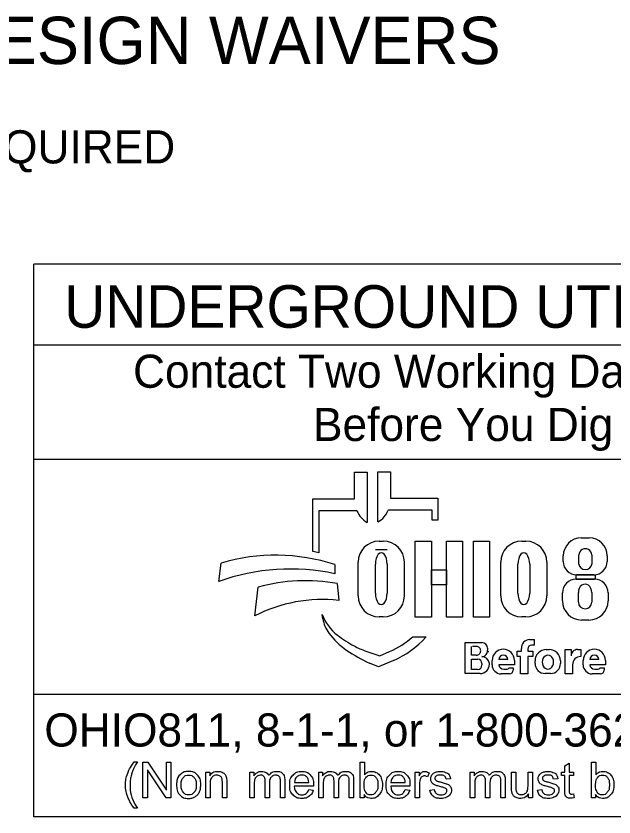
# Model space of a CAD drawing. Extents: x 43.1 to 77.1, y 2.7 to 24.7.
# Drawn here: x 46.033 to 48.562, y 4.801 to 8.187 of the extents above; entities that cross this region are included whole.
import ezdxf

# ---------------------------------------------------------------- set-up
doc = ezdxf.new("R2010")
doc.units = 0
doc.layers.add('SH_Data', color=7, linetype='Continuous')
doc.layers.add('SH_Text', color=7, linetype='Continuous')

msp = doc.modelspace()

# ---------------------------------------------------------------- linework, layer by layer
at = {"layer": 'SH_Data'}
for p, q in [((46.1084, 4.8008), (46.1084, 7.1383)), ((50.3584, 7.1383), (46.1084, 7.1383)), ((46.1084, 6.7967), (50.3584, 6.7967)), ((46.1084, 6.3134), (50.3584, 6.3134)), ((50.3584, 5.3187), (46.1084, 5.3187)), ((50.3584, 4.8008), (46.1084, 4.8008))]:
    msp.add_line(p, q, dxfattribs=at)
at = {"layer": 'SH_Text'}
for p, q in [((47.4645, 6.1463), (47.4645, 6.2578)), ((47.4645, 6.2578), (47.5181, 6.2578)), ((47.5181, 6.2578), (47.5181, 6.0457)), ((47.5638, 6.0481), (47.5638, 6.2601)), ((47.5638, 6.2601), (47.6174, 6.2601)), ((47.6174, 6.2601), (47.6174, 6.1487)), ((47.2885, 5.9224), (47.2885, 6.1463)), ((47.2885, 6.1463), (47.4645, 6.1463)), ((47.6174, 6.1487), (47.8167, 6.1487)), ((47.8167, 6.1487), (47.8167, 6.0548)), ((47.3137, 6.0949), (47.3137, 5.918)), ((47.4749, 6.0949), (47.3137, 6.0949)), ((47.7934, 6.0972), (47.607, 6.0972)), ((47.7934, 6.0548), (47.7934, 6.0972)), ((47.8167, 6.0548), (47.7934, 6.0548)), ((47.5694, 5.9671), (47.586, 5.9671)), ((48.1725, 5.9671), (48.189, 5.9671)), ((48.424, 5.9811), (48.4568, 5.9811)), ((47.6027, 5.9301), (47.5529, 5.9301)), ((48.3477, 5.8805), (48.3477, 5.9048)), ((48.4139, 5.8691), (48.4139, 5.9084)), ((48.468, 5.9084), (48.468, 5.8691)), ((48.5331, 5.9048), (48.5331, 5.8805)), ((46.8911, 5.7961), (46.9005, 5.8743)), ((47.3818, 5.8678), (47.3818, 5.8289)), ((47.48, 5.7357), (47.48, 5.8777)), ((47.5529, 5.7471), (47.5529, 5.8694)), ((47.6027, 5.8694), (47.6027, 5.7471)), ((47.6754, 5.8777), (47.6754, 5.7357)), ((48.083, 5.7357), (48.083, 5.8777)), ((48.1559, 5.7471), (48.1559, 5.8694)), ((48.2057, 5.8694), (48.2057, 5.7471)), ((48.2785, 5.8777), (48.2785, 5.7357)), ((48.4771, 5.8245), (48.4037, 5.8245)), ((48.4019, 5.8062), (48.4792, 5.8062)), ((47.043, 5.6516), (47.0576, 5.7717)), ((47.3918, 5.7872), (47.398, 5.7162)), ((48.344, 5.7143), (48.344, 5.7483)), ((48.4115, 5.7083), (48.4115, 5.7493)), ((48.4684, 5.7493), (48.4684, 5.7083)), ((48.5371, 5.7483), (48.5371, 5.7143)), ((47.3306, 5.6387), (47.3276, 5.6566)), ((47.586, 5.6462), (47.5694, 5.6462)), ((48.189, 5.6462), (48.1725, 5.6462)), ((48.4562, 5.6334), (48.425, 5.6334)), ((47.7109, 5.5628), (47.7684, 5.5628)), ((47.9322, 5.4071), (47.9322, 5.5378)), ((47.9322, 5.5378), (48.0034, 5.5378)), ((47.9602, 5.4843), (47.9602, 5.5212)), ((47.9854, 5.5212), (47.9641, 5.5212)), ((48.2048, 5.5506), (48.2243, 5.5506)), ((48.2243, 5.5271), (48.2141, 5.5271)), ((48.2243, 5.5506), (48.2243, 5.5276)), ((47.5125, 5.5024), (47.5719, 5.482)), ((47.5719, 5.482), (47.613, 5.4998)), ((48.0272, 5.514), (48.0272, 5.5061)), ((48.1522, 5.4792), (48.1522, 5.5022)), ((48.1522, 5.5022), (48.1715, 5.5022)), ((48.1715, 5.5022), (48.1715, 5.5127)), ((48.1976, 5.5106), (48.1976, 5.5022)), ((48.1976, 5.5022), (48.2192, 5.5022)), ((48.2192, 5.5022), (48.2192, 5.4792)), ((48.276, 5.5088), (48.2882, 5.5088)), ((48.3563, 5.4059), (48.3563, 5.5086)), ((48.3563, 5.5086), (48.3808, 5.5086)), ((48.3808, 5.5086), (48.3808, 5.4817)), ((48.4081, 5.5086), (48.422, 5.5086)), ((48.422, 5.5086), (48.422, 5.4789)), ((47.5659, 5.4349), (47.5286, 5.4514)), ((47.6292, 5.4624), (47.5659, 5.4349)), ((47.9796, 5.4843), (47.9602, 5.4843)), ((47.9602, 5.4249), (47.9602, 5.4678)), ((47.9602, 5.4678), (47.9857, 5.4678)), ((48.0468, 5.4438), (48.0468, 5.4623)), ((48.1134, 5.4662), (48.0748, 5.4662)), ((48.1413, 5.4623), (48.1413, 5.4446)), ((48.1671, 5.4792), (48.1522, 5.4792)), ((48.1671, 5.4059), (48.1671, 5.4792)), ((48.2192, 5.4792), (48.1976, 5.4792)), ((48.1976, 5.4792), (48.1976, 5.4059)), ((48.2282, 5.4502), (48.2282, 5.461)), ((48.336, 5.461), (48.336, 5.4502)), ((48.4317, 5.4438), (48.4317, 5.4623)), ((48.4983, 5.4662), (48.4598, 5.4662)), ((48.5262, 5.4623), (48.5262, 5.4446)), ((47.9855, 5.4249), (47.9602, 5.4249)), ((48.0039, 5.4496), (48.0039, 5.4433)), ((48.0352, 5.4467), (48.0352, 5.4464)), ((48.1413, 5.4446), (48.0749, 5.4446)), ((48.0958, 5.4254), (48.1099, 5.4254)), ((48.1185, 5.4309), (48.1354, 5.4309)), ((48.1354, 5.4309), (48.1354, 5.4211)), ((48.3868, 5.444), (48.3868, 5.4059)), ((48.5262, 5.4446), (48.4598, 5.4446)), ((48.4807, 5.4254), (48.4949, 5.4254)), ((48.5034, 5.4309), (48.5203, 5.4309)), ((48.5203, 5.4309), (48.5203, 5.4211)), ((47.9959, 5.4071), (47.9322, 5.4071)), ((48.1201, 5.4059), (48.0847, 5.4059)), ((48.1976, 5.4059), (48.1671, 5.4059)), ((48.2932, 5.4074), (48.271, 5.4074)), ((48.3868, 5.4059), (48.3563, 5.4059)), ((48.5051, 5.4059), (48.4697, 5.4059))]:
    msp.add_line(p, q, dxfattribs=at)
for points in [[(47.7219, 5.9661), (47.7898, 5.9661), (47.7898, 5.6461), (47.7219, 5.6461)], [(47.854, 5.9661), (47.922, 5.9661), (47.922, 5.6461), (47.854, 5.6461)], [(47.9673, 5.9661), (48.0361, 5.9661), (48.0361, 5.6461), (47.9673, 5.6461)], [(47.7898, 5.8462), (47.854, 5.8462), (47.854, 5.7822), (47.7898, 5.7822)], [(48.4016, 5.8246), (48.4832, 5.8246), (48.4832, 5.8061), (48.4016, 5.8061)]]:
    msp.add_lwpolyline(points, close=True, dxfattribs=at)
for points in [[(46.533, 5.0346), (46.5462, 5.0346)], [(46.5698, 4.8819), (46.5698, 5.0321), (46.5901, 5.0321), (46.6691, 4.9142), (46.6691, 5.0321), (46.6881, 5.0321), (46.6881, 4.8819), (46.6678, 4.8819), (46.5888, 4.9999), (46.5888, 4.8819), (46.5698, 4.8819)], [(47.5052, 4.8819), (47.4882, 4.8819), (47.4882, 5.0321), (47.5066, 5.0321), (47.5066, 4.9786)], [(48.3542, 4.9138), (48.3542, 4.9765), (48.3406, 4.9765), (48.3406, 4.9908), (48.3542, 4.9908), (48.3542, 5.0177), (48.3726, 5.0288), (48.3726, 4.9908), (48.391, 4.9908), (48.391, 4.9765), (48.3726, 4.9765), (48.3726, 4.9127)], [(48.4843, 4.8819), (48.4673, 4.8819), (48.4673, 5.0321), (48.4857, 5.0321), (48.4857, 4.9786)], [(46.8357, 4.8819), (46.8357, 4.9908), (46.8523, 4.9908), (46.8523, 4.9753)], [(47.0222, 4.8819), (47.0222, 4.9908), (47.0386, 4.9908), (47.0386, 4.9754)], [(47.3135, 4.8819), (47.3135, 4.9908), (47.33, 4.9908), (47.33, 4.9754)], [(47.7213, 4.8819), (47.7213, 4.9908), (47.7379, 4.9908), (47.7379, 4.9743)], [(47.7804, 4.9873), (47.7739, 4.9702)], [(47.9545, 4.8819), (47.9545, 4.9908), (47.971, 4.9908), (47.971, 4.9754)], [(48.1288, 4.9234), (48.1288, 4.9908), (48.1473, 4.9908), (48.1473, 4.9305)], [(48.1985, 4.9325), (48.1985, 4.9908), (48.217, 4.9908), (48.217, 4.8819), (48.2005, 4.8819)], [(46.9241, 4.9488), (46.9241, 4.8819), (46.9057, 4.8819), (46.9057, 4.9481)], [(47.1052, 4.9451), (47.1052, 4.8819), (47.0868, 4.8819), (47.0868, 4.9526)], [(47.1697, 4.9566), (47.1697, 4.8819), (47.1512, 4.8819), (47.1512, 4.9504)], [(47.2108, 4.9467), (47.2715, 4.9467)], [(47.3966, 4.9451), (47.3966, 4.8819), (47.3782, 4.8819), (47.3782, 4.9526)], [(47.461, 4.9566), (47.461, 4.8819), (47.4426, 4.8819), (47.4426, 4.9504)], [(47.6188, 4.9467), (47.6795, 4.9467)], [(47.8703, 4.9626), (47.8522, 4.9602)], [(48.0376, 4.9451), (48.0376, 4.8819), (48.0192, 4.8819), (48.0192, 4.9526)], [(48.102, 4.9566), (48.102, 4.8819), (48.0836, 4.8819), (48.0836, 4.9504)], [(48.3249, 4.9626), (48.3068, 4.9602)], [(46.8542, 4.9413), (46.8542, 4.8819), (46.8357, 4.8819)], [(47.0406, 4.9384), (47.0406, 4.8819), (47.0222, 4.8819)], [(47.2909, 4.9316), (47.2097, 4.9316)], [(47.2713, 4.9171), (47.2904, 4.9147)], [(47.332, 4.9384), (47.332, 4.8819), (47.3135, 4.8819)], [(47.6989, 4.9316), (47.6177, 4.9316)], [(47.6793, 4.9171), (47.6984, 4.9147)], [(47.7397, 4.9389), (47.7397, 4.8819), (47.7213, 4.8819)], [(47.7839, 4.9145), (47.8021, 4.9173)], [(47.973, 4.9384), (47.973, 4.8819), (47.9545, 4.8819)], [(48.2385, 4.9145), (48.2567, 4.9173)], [(47.5052, 4.8956), (47.5052, 4.8819)], [(48.2005, 4.8819), (48.2005, 4.898)], [(48.391, 4.8984), (48.3937, 4.8821)], [(48.4843, 4.8956), (48.4843, 4.8819)], [(46.5462, 4.8378), (46.533, 4.8378)]]:
    msp.add_lwpolyline(points, dxfattribs=at)
for centre, radius, start, end in [((47.5662, 6.1317), 0.0985, 201.9296, 240.7469), ((47.5156, 6.134), 0.0985, 299.2531, 338.0704), ((47.5694, 5.8777), 0.0895, 90, 180), ((47.586, 5.8777), 0.0895, 0, 90), ((48.1725, 5.8777), 0.0895, 90, 180), ((48.189, 5.8777), 0.0895, 0, 90), ((48.424, 5.9048), 0.0763, 90, 180), ((48.4568, 5.9048), 0.0763, 0, 90), ((47.1306, 5.0882), 0.8191, 72.1402, 106.3144), ((47.1604, 5.1135), 0.8191, 79.2074, 81.0007), ((48.4037, 5.8805), 0.056, 180, 270), ((48.4771, 5.8805), 0.056, 270, 0), ((47.1937, 4.9571), 0.8919, 77.8238, 109.8274), ((47.2576, 5.0674), 0.7322, 79.44, 105.8467), ((48.4019, 5.7483), 0.0579, 90, 180), ((48.4792, 5.7483), 0.0579, 0, 90), ((47.5694, 5.7357), 0.0895, 180, 270), ((47.586, 5.7357), 0.0895, 270, 0), ((48.1725, 5.7357), 0.0895, 180, 270), ((48.189, 5.7357), 0.0895, 270, 0), ((47.3296, 5.0842), 0.6357, 83.8248, 116.8021), ((48.425, 5.7143), 0.081, 180, 270), ((48.4562, 5.7143), 0.081, 270, 0), ((47.515, 5.7287), 0.2008, 201.0457, 232.5314), ((47.4719, 5.6628), 0.1433, 189.6817, 216.0884), ((47.6056, 5.7602), 0.3088, 216.0884, 235.7167), ((47.7075, 5.9799), 0.5173, 232.5314, 241.794), ((47.4696, 5.8302), 0.3602, 293.4582, 312.0712), ((47.4696, 5.8302), 0.401, 293.4582, 317.8286), ((47.6223, 5.8211), 0.3371, 241.794, 250.9821), ((47.9815, 5.5044), 0.0169, 357.8325, 90), ((48.0034, 5.514), 0.0238, 0, 90), ((48.2048, 5.517), 0.0335, 90, 187.5187), ((48.2141, 5.5106), 0.0165, 90, 180), ((47.7721, 6.0045), 0.6044, 235.7167, 246.2325), ((47.9796, 5.503), 0.0187, 270, 2.0582), ((48.003, 5.5033), 0.0243, 270, 6.6529), ((48.0136, 5.5018), 0.0175, 347.4023, 0), ((48.094, 5.4623), 0.0473, 0, 180), ((48.276, 5.461), 0.0478, 90, 180), ((48.2882, 5.461), 0.0478, 0, 90), ((48.4077, 5.4817), 0.0269, 89.2449, 180), ((48.479, 5.4623), 0.0473, 0, 180), ((47.9857, 5.4496), 0.0181, 0, 90), ((48.0031, 5.4469), 0.0321, 4.0748, 90), ((48.0023, 5.4467), 0.033, 0, 11.7502), ((48.0941, 5.4652), 0.0193, 2.9632, 177.0368), ((48.4217, 5.444), 0.0349, 89.6033, 180), ((48.479, 5.4652), 0.0193, 2.9632, 177.0368), ((47.9855, 5.4433), 0.0184, 270, 0), ((47.9959, 5.4464), 0.0393, 270, 0), ((48.0847, 5.4438), 0.038, 180, 270), ((48.0958, 5.4464), 0.021, 184.827, 270), ((48.1099, 5.4347), 0.00938, 270, 335.9979), ((48.1201, 5.4211), 0.0152, 270, 0), ((48.271, 5.4502), 0.0428, 180, 270), ((48.2932, 5.4502), 0.0428, 270, 0), ((48.4697, 5.4438), 0.038, 180, 270), ((48.4807, 5.4464), 0.021, 184.827, 270), ((48.4949, 5.4347), 0.00938, 270, 335.9979), ((48.5051, 5.4211), 0.0152, 270, 0)]:
    msp.add_arc(centre, radius, start, end, dxfattribs=at)
for centre, major_axis, ratio, start_param, end_param in [((48.4409, 5.9084), (0.0271, 0), 0.969373, 0, 3.141593), ((47.5778, 5.8694), (0, 0.0484), 0.514403, 4.712389, 7.853982), ((48.1808, 5.8694), (0, 0.0484), 0.514403, 4.712389, 7.853982), ((48.4409, 5.8691), (0.0271, 0), 0.818453, 3.141593, 6.283185), ((48.4399, 5.7493), (0, 0.0358), 0.794529, 4.712389, 7.853982), ((47.5778, 5.7471), (0, 0.0484), 0.514403, 1.570796, 4.712389), ((48.1808, 5.7471), (0, 0.0484), 0.514403, 1.570796, 4.712389), ((48.4399, 5.7083), (0.0284, 0), 0.959837, 3.141593, 6.283185), ((48.2826, 5.4556), (0, 0.029), 0.832186, 4.712389, 7.853982), ((48.2826, 5.4556), (0, 0.0302), 0.797287, 1.570796, 4.712389)]:
    msp.add_ellipse(centre, major_axis=major_axis, ratio=ratio, start_param=start_param, end_param=end_param, dxfattribs=at)
for points in [[(46.533, 4.8378), (46.5178, 4.857), (46.5072, 4.8828), (46.4966, 4.9086), (46.4966, 4.9363), (46.4966, 4.9607), (46.5045, 4.983), (46.5138, 5.0089), (46.533, 5.0346)], [(46.5462, 5.0346), (46.5338, 5.0133), (46.5299, 5.0042), (46.5236, 4.9901), (46.52, 4.9747), (46.5156, 4.9556), (46.5156, 4.9362), (46.5156, 4.8869), (46.5462, 4.8378)], [(46.7123, 4.9364), (46.7123, 4.9666), (46.729, 4.9811), (46.7431, 4.9932), (46.7632, 4.9932), (46.7857, 4.9932), (46.7999, 4.9785), (46.8141, 4.9638), (46.8141, 4.9379), (46.8141, 4.9169), (46.8078, 4.9049), (46.8015, 4.8929), (46.7895, 4.8862), (46.7775, 4.8795), (46.7632, 4.8795), (46.7404, 4.8795), (46.7263, 4.8942), (46.7123, 4.9088), (46.7123, 4.9364)], [(46.7313, 4.9364), (46.7313, 4.9155), (46.7404, 4.9051), (46.7494, 4.8947), (46.7632, 4.8947), (46.7769, 4.8947), (46.786, 4.9051), (46.7951, 4.9156), (46.7951, 4.937), (46.7951, 4.9572), (46.786, 4.9676), (46.7768, 4.978), (46.7632, 4.978), (46.7494, 4.978), (46.7404, 4.9676), (46.7313, 4.9573), (46.7313, 4.9364)], [(46.8523, 4.9753), (46.8643, 4.9932), (46.8869, 4.9932), (46.8968, 4.9932), (46.905, 4.9897), (46.9132, 4.9861), (46.9173, 4.9804), (46.9214, 4.9746), (46.9231, 4.9668), (46.9241, 4.9616), (46.9241, 4.9488)], [(46.9057, 4.9481), (46.9057, 4.9594), (46.9035, 4.9649), (46.9014, 4.9705), (46.8959, 4.9738), (46.8904, 4.9772), (46.883, 4.9772), (46.8713, 4.9772), (46.8627, 4.9697), (46.8542, 4.9622), (46.8542, 4.9413)], [(47.0386, 4.9754), (47.0438, 4.9834), (47.0523, 4.9883), (47.0608, 4.9932), (47.0716, 4.9932), (47.0837, 4.9932), (47.0915, 4.9882), (47.0992, 4.9831), (47.1024, 4.9741), (47.1153, 4.9932), (47.136, 4.9932), (47.1522, 4.9932), (47.161, 4.9842), (47.1697, 4.9753), (47.1697, 4.9566)], [(47.0868, 4.9526), (47.0868, 4.9649), (47.0823, 4.971), (47.0778, 4.9772), (47.0675, 4.9772), (47.0598, 4.9772), (47.0531, 4.9731), (47.0465, 4.969), (47.0436, 4.9611), (47.0406, 4.9532), (47.0406, 4.9384)], [(47.1512, 4.9504), (47.1512, 4.9615), (47.1495, 4.9664), (47.1477, 4.9712), (47.1429, 4.9742), (47.1382, 4.9772), (47.1319, 4.9772), (47.1204, 4.9772), (47.1128, 4.9695), (47.1052, 4.9619), (47.1052, 4.9451)], [(47.2904, 4.9147), (47.2859, 4.898), (47.2737, 4.8888), (47.2615, 4.8795), (47.2426, 4.8795), (47.2187, 4.8795), (47.2047, 4.8942), (47.1907, 4.9089), (47.1907, 4.9354), (47.1907, 4.9629), (47.2049, 4.978), (47.219, 4.9932), (47.2415, 4.9932), (47.2634, 4.9932), (47.2772, 4.9783), (47.291, 4.9635), (47.291, 4.9365), (47.291, 4.9349), (47.2909, 4.9316)], [(47.2715, 4.9467), (47.2703, 4.9605), (47.2646, 4.9674), (47.2558, 4.9781), (47.2417, 4.9781), (47.229, 4.9781), (47.2204, 4.9695), (47.2117, 4.961), (47.2108, 4.9467)], [(47.33, 4.9754), (47.3351, 4.9834), (47.3436, 4.9883), (47.3521, 4.9932), (47.363, 4.9932), (47.3751, 4.9932), (47.3828, 4.9882), (47.3906, 4.9831), (47.3937, 4.9741), (47.4067, 4.9932), (47.4274, 4.9932), (47.4436, 4.9932), (47.4523, 4.9842), (47.461, 4.9753), (47.461, 4.9566)], [(47.3782, 4.9526), (47.3782, 4.9649), (47.3737, 4.971), (47.3692, 4.9772), (47.3589, 4.9772), (47.3511, 4.9772), (47.3445, 4.9731), (47.3379, 4.969), (47.3349, 4.9611), (47.332, 4.9532), (47.332, 4.9384)], [(47.4426, 4.9504), (47.4426, 4.9615), (47.4408, 4.9664), (47.439, 4.9712), (47.4343, 4.9742), (47.4296, 4.9772), (47.4233, 4.9772), (47.4118, 4.9772), (47.4042, 4.9695), (47.3966, 4.9619), (47.3966, 4.9451)], [(47.505, 4.9372), (47.505, 4.9176), (47.5103, 4.9089), (47.519, 4.8947), (47.5338, 4.8947), (47.5459, 4.8947), (47.5547, 4.9052), (47.5635, 4.9157), (47.5635, 4.9365), (47.5635, 4.9578), (47.5551, 4.9679), (47.5466, 4.9781), (47.5347, 4.9781), (47.5226, 4.9781), (47.5138, 4.9676), (47.505, 4.9571), (47.505, 4.9372)], [(47.5066, 4.9786), (47.5183, 4.9932), (47.5364, 4.9932), (47.5464, 4.9932), (47.5554, 4.9891), (47.5644, 4.9851), (47.5702, 4.9778), (47.5759, 4.9705), (47.5792, 4.9601), (47.5825, 4.9498), (47.5825, 4.938), (47.5825, 4.9101), (47.5687, 4.8948), (47.5548, 4.8795), (47.5355, 4.8795), (47.5162, 4.8795), (47.5052, 4.8956)], [(47.6984, 4.9147), (47.6939, 4.898), (47.6817, 4.8888), (47.6695, 4.8795), (47.6506, 4.8795), (47.6267, 4.8795), (47.6127, 4.8942), (47.5987, 4.9089), (47.5987, 4.9354), (47.5987, 4.9629), (47.6129, 4.978), (47.627, 4.9932), (47.6495, 4.9932), (47.6713, 4.9932), (47.6852, 4.9783), (47.699, 4.9635), (47.699, 4.9365), (47.699, 4.9349), (47.6989, 4.9316)], [(47.6795, 4.9467), (47.6783, 4.9605), (47.6726, 4.9674), (47.6638, 4.9781), (47.6497, 4.9781), (47.637, 4.9781), (47.6284, 4.9695), (47.6197, 4.961), (47.6188, 4.9467)], [(47.7379, 4.9743), (47.7442, 4.9858), (47.7496, 4.9895), (47.755, 4.9932), (47.7614, 4.9932), (47.7707, 4.9932), (47.7804, 4.9873)], [(47.8522, 4.9602), (47.851, 4.9686), (47.8451, 4.9734), (47.8392, 4.9781), (47.8284, 4.9781), (47.8157, 4.9781), (47.8103, 4.9739), (47.8049, 4.9697), (47.8049, 4.964), (47.8049, 4.9604), (47.8071, 4.9576), (47.8094, 4.9546), (47.8142, 4.9526), (47.817, 4.9516), (47.8305, 4.9479), (47.8501, 4.9427), (47.8578, 4.9394), (47.8656, 4.936), (47.87, 4.9297), (47.8744, 4.9234), (47.8744, 4.9139), (47.8744, 4.9047), (47.869, 4.8966), (47.8637, 4.8885), (47.8535, 4.884), (47.8433, 4.8795), (47.8305, 4.8795), (47.8093, 4.8795), (47.7981, 4.8883), (47.787, 4.8972), (47.7839, 4.9145)], [(47.8021, 4.9173), (47.8036, 4.9063), (47.8107, 4.9005), (47.8177, 4.8947), (47.8304, 4.8947), (47.8431, 4.8947), (47.8493, 4.8998), (47.8554, 4.905), (47.8554, 4.912), (47.8554, 4.9182), (47.85, 4.9218), (47.8462, 4.9243), (47.8311, 4.9281), (47.8108, 4.9332), (47.803, 4.937), (47.7951, 4.9407), (47.7911, 4.9473), (47.787, 4.9539), (47.787, 4.9619), (47.787, 4.9691), (47.7903, 4.9753), (47.7937, 4.9815), (47.7994, 4.9856), (47.8037, 4.9888), (47.8112, 4.991), (47.8186, 4.9932), (47.8271, 4.9932), (47.8399, 4.9932), (47.8496, 4.9895), (47.8593, 4.9858), (47.864, 4.9795), (47.8686, 4.9732), (47.8703, 4.9626)], [(47.971, 4.9754), (47.9761, 4.9834), (47.9846, 4.9883), (47.9931, 4.9932), (48.004, 4.9932), (48.0161, 4.9932), (48.0238, 4.9882), (48.0316, 4.9831), (48.0347, 4.9741), (48.0477, 4.9932), (48.0684, 4.9932), (48.0846, 4.9932), (48.0933, 4.9842), (48.102, 4.9753), (48.102, 4.9566)], [(48.0192, 4.9526), (48.0192, 4.9649), (48.0147, 4.971), (48.0102, 4.9772), (47.9999, 4.9772), (47.9921, 4.9772), (47.9855, 4.9731), (47.9789, 4.969), (47.9759, 4.9611), (47.973, 4.9532), (47.973, 4.9384)], [(48.0836, 4.9504), (48.0836, 4.9615), (48.0818, 4.9664), (48.08, 4.9712), (48.0753, 4.9742), (48.0706, 4.9772), (48.0643, 4.9772), (48.0528, 4.9772), (48.0452, 4.9695), (48.0376, 4.9619), (48.0376, 4.9451)], [(48.3068, 4.9602), (48.3056, 4.9686), (48.2997, 4.9734), (48.2938, 4.9781), (48.283, 4.9781), (48.2703, 4.9781), (48.2649, 4.9739), (48.2594, 4.9697), (48.2594, 4.964), (48.2594, 4.9604), (48.2617, 4.9576), (48.2639, 4.9546), (48.2688, 4.9526), (48.2715, 4.9516), (48.2851, 4.9479), (48.3047, 4.9427), (48.3124, 4.9394), (48.3202, 4.936), (48.3246, 4.9297), (48.329, 4.9234), (48.329, 4.9139), (48.329, 4.9047), (48.3236, 4.8966), (48.3182, 4.8885), (48.3081, 4.884), (48.2979, 4.8795), (48.2851, 4.8795), (48.2638, 4.8795), (48.2527, 4.8883), (48.2416, 4.8972), (48.2385, 4.9145)], [(48.2567, 4.9173), (48.2582, 4.9063), (48.2653, 4.9005), (48.2723, 4.8947), (48.2849, 4.8947), (48.2977, 4.8947), (48.3038, 4.8998), (48.31, 4.905), (48.31, 4.912), (48.31, 4.9182), (48.3046, 4.9218), (48.3008, 4.9243), (48.2857, 4.9281), (48.2654, 4.9332), (48.2575, 4.937), (48.2497, 4.9407), (48.2456, 4.9473), (48.2416, 4.9539), (48.2416, 4.9619), (48.2416, 4.9691), (48.2449, 4.9753), (48.2482, 4.9815), (48.254, 4.9856), (48.2583, 4.9888), (48.2657, 4.991), (48.2732, 4.9932), (48.2817, 4.9932), (48.2945, 4.9932), (48.3042, 4.9895), (48.3139, 4.9858), (48.3185, 4.9795), (48.3231, 4.9732), (48.3249, 4.9626)], [(48.4841, 4.9372), (48.4841, 4.9176), (48.4894, 4.9089), (48.4981, 4.8947), (48.5129, 4.8947), (48.525, 4.8947), (48.5338, 4.9052), (48.5426, 4.9157), (48.5426, 4.9365), (48.5426, 4.9578), (48.5341, 4.9679), (48.5257, 4.9781), (48.5137, 4.9781), (48.5017, 4.9781), (48.4929, 4.9676), (48.4841, 4.9571), (48.4841, 4.9372)], [(48.4857, 4.9786), (48.4974, 4.9932), (48.5155, 4.9932), (48.5255, 4.9932), (48.5345, 4.9891), (48.5434, 4.9851), (48.5492, 4.9778), (48.555, 4.9705), (48.5583, 4.9601), (48.5616, 4.9498), (48.5616, 4.938), (48.5616, 4.9101), (48.5477, 4.8948), (48.5339, 4.8795), (48.5145, 4.8795), (48.4953, 4.8795), (48.4843, 4.8956)], [(47.7739, 4.9702), (47.7672, 4.9742), (47.7605, 4.9742), (47.7544, 4.9742), (47.7496, 4.9706), (47.7449, 4.9669), (47.7428, 4.9605), (47.7397, 4.9506), (47.7397, 4.9389)], [(47.2097, 4.9316), (47.2108, 4.9137), (47.2199, 4.9042), (47.229, 4.8947), (47.2426, 4.8947), (47.2528, 4.8947), (47.26, 4.9), (47.2671, 4.9054), (47.2713, 4.9171)], [(47.6177, 4.9316), (47.6188, 4.9137), (47.6279, 4.9042), (47.637, 4.8947), (47.6506, 4.8947), (47.6608, 4.8947), (47.668, 4.9), (47.6751, 4.9054), (47.6793, 4.9171)], [(48.2005, 4.898), (48.1878, 4.8795), (48.166, 4.8795), (48.1564, 4.8795), (48.148, 4.8832), (48.1397, 4.8869), (48.1356, 4.8925), (48.1316, 4.8981), (48.13, 4.9062), (48.1288, 4.9116), (48.1288, 4.9234)], [(48.1473, 4.9305), (48.1473, 4.916), (48.1484, 4.911), (48.1501, 4.9037), (48.1558, 4.8996), (48.1614, 4.8955), (48.1697, 4.8955), (48.178, 4.8955), (48.1852, 4.8997), (48.1925, 4.904), (48.1955, 4.9113), (48.1985, 4.9186), (48.1985, 4.9325)], [(48.3937, 4.8821), (48.3859, 4.8805), (48.3798, 4.8805), (48.3697, 4.8805), (48.3642, 4.8836), (48.3587, 4.8868), (48.3564, 4.892), (48.3542, 4.8972), (48.3542, 4.9138)], [(48.3726, 4.9127), (48.3726, 4.9048), (48.3736, 4.9026), (48.3745, 4.9003), (48.3767, 4.899), (48.3789, 4.8976), (48.383, 4.8976), (48.386, 4.8976), (48.391, 4.8984)]]:
    msp.add_open_spline(points, degree=3, dxfattribs=at)

# ---------------------------------------------------------------- texts
for s, height, p in [('ADA DESIGN WAIVERS', 0.2, (45.1253, 7.9836)), ('NONE REQUIRED', 0.14, (45.1253, 7.5636)), ('UNDERGROUND UTILITIES', 0.18, (46.2366, 6.8687)), ('Contact Two Working Days', 0.14, (46.5281, 6.6152)), ('Before You Dig', 0.14, (47.2892, 6.3902)), ('OHIO811, 8-1-1, or 1-800-362-2764', 0.14, (46.1529, 5.0986))]:
    msp.add_text(s, height=height, dxfattribs=at).set_placement(p)

doc.saveas('drawing.dxf')
